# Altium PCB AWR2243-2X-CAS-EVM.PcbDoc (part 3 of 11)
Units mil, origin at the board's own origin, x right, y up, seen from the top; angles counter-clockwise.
Board outline 5118.11 x 3937.01 mil, 8 copper layers (Layer 1 - Top Layer, Layer 2 - GND, Layer 3 - Signal (Sensitive), Layer 4 - GND / Signal, Layer 5 - Signal, Layer 6 - PWR / Signal, Layer 7 - GND, Layer 8 - Bottom Layer), stack 54.8 mil thick; 629 components, 407 nets, 2243 pads, 3950 vias.
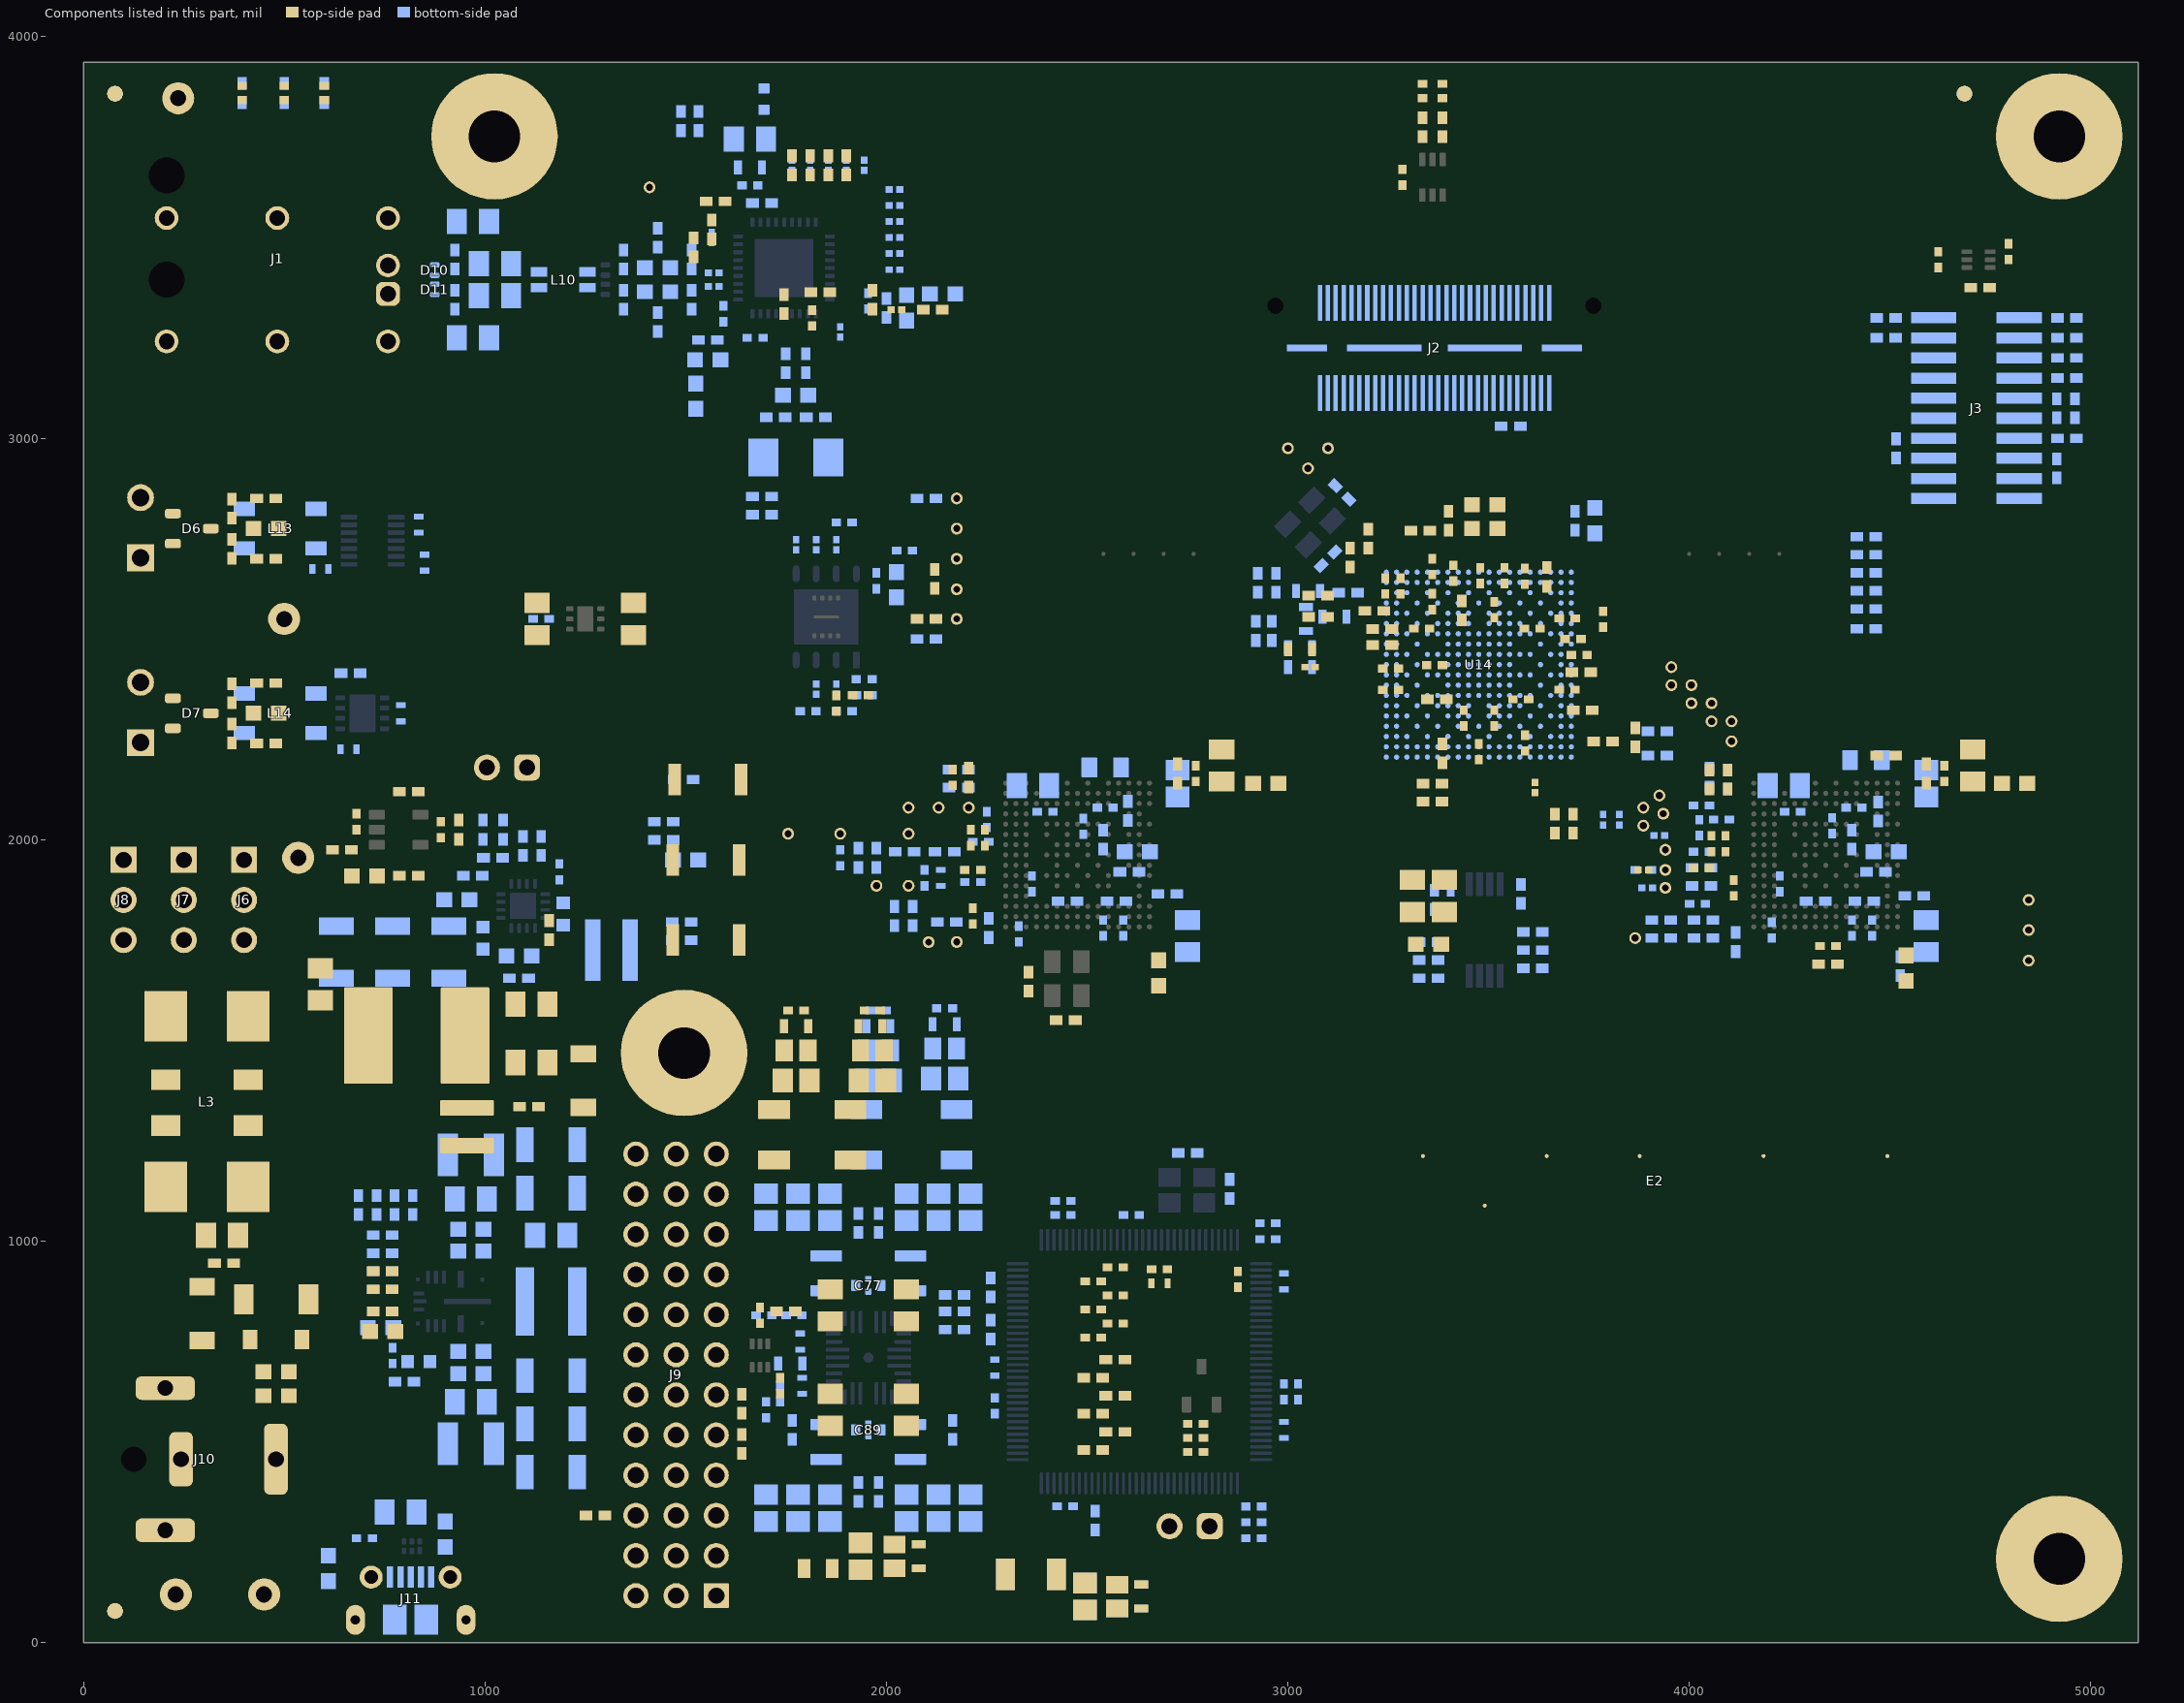
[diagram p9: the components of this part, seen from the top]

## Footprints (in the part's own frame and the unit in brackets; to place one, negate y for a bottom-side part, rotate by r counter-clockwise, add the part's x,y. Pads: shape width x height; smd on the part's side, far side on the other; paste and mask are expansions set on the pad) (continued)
Samtec_FTR-110-51-x-D-06 [mm] "Header, 1.27mm, 10x2, SMT"
  rect 2.87x0.711 smd: 1(-2.705,5.715) 2(2.705,5.715) 3(-2.705,4.445) 4(2.705,4.445) 5(-2.705,3.175) 6(2.705,3.175) 7(-2.705,1.905) 8(2.705,1.905) 9(-2.705,0.635) 10(2.705,0.635) 11(-2.705,-0.635) 12(2.705,-0.635) 13(-2.705,-1.905) 14(2.705,-1.905) 15(-2.705,-3.175) 16(2.705,-3.175) 17(-2.705,-4.445) 18(2.705,-4.445) 19(-2.705,-5.715) 20(2.705,-5.715)
  silkscreen extent -2.49,-6.35 2.49,6.7, body extent -3.76,-6.35 3.76,6.35, height 8.64
Samtec_QSH-030-01-X-D-A [mm] "Receptacle, 0.5 mm, 30x2, TH"
  rect 2.27x0.279 smd: 1(-2.865,7.25) 2(2.865,7.25) 3(-2.865,6.75) 4(2.865,6.75) 5(-2.865,6.25) 6(2.865,6.25) 7(-2.865,5.75) 8(2.865,5.75) 9(-2.865,5.25) 10(2.865,5.25) 11(-2.865,4.75) 12(2.865,4.75) 13(-2.865,4.25) 14(2.865,4.25) 15(-2.865,3.75) 16(2.865,3.75) 17(-2.865,3.25) 18(2.865,3.25) 19(-2.865,2.75) 20(2.865,2.75) 21(-2.865,2.25) 22(2.865,2.25) 23(-2.865,1.75) 24(2.865,1.75) 25(-2.865,1.25) 26(2.865,1.25) 27(-2.865,0.75) 28(2.865,0.75) 29(-2.865,0.25) 30(2.865,0.25) 31(-2.865,-0.25) 32(2.865,-0.25) 33(-2.865,-0.75) 34(2.865,-0.75) 35(-2.865,-1.25) 36(2.865,-1.25) 37(-2.865,-1.75) 38(2.865,-1.75) 39(-2.865,-2.25) 40(2.865,-2.25) 41(-2.865,-2.75) 42(2.865,-2.75) 43(-2.865,-3.25) 44(2.865,-3.25) 45(-2.865,-3.75) 46(2.865,-3.75) 47(-2.865,-4.25) 48(2.865,-4.25) 49(-2.865,-4.75) 50(2.865,-4.75) 51(-2.865,-5.25) 52(2.865,-5.25) 53(-2.865,-5.75) 54(2.865,-5.75) 55(-2.865,-6.25) 56(2.865,-6.25) 57(-2.865,-6.75) 58(2.865,-6.75) 59(-2.865,-7.25) 60(2.865,-7.25)
  round 0 hole 1.02 unplated: MH1(2.67,10.065) MH2(2.67,-10.065)
  rect 0.43x2.54 smd: MP1(0,8.065) MP4(0,-8.065)
  rect 0.43x4.7 smd: MP2(0,3.175) MP3(0,-3.175)
  silkscreen extent -3.9,-10.66 3.62,10.66, body extent -3.75,-10.64 3.75,10.67, height 3.25
SMAF [mm] "SMD, 2-Leads, Body 3.8x2.5mm"
  rect 1.24x1.89 smd: 1(-2.04,0) 2(2.04,0)
  silkscreen extent -3.4,-1.3 2.8,1.3, body extent -2.35,-1.25 2.35,1.25, height 1
SML-P1_GREEN [mm] "ROHM"
  rect 0.5x0.6 smd: 1(-0.45,0) 2(0.45,0)
  silkscreen extent -0.95,-0.3 -0.95,0.3, body extent -0.53,-0.33 0.53,0.33, height 0.25
SOD-123 [mm] "On Semi recommended land pattern"
  rect 0.915x1.22 smd: 1(-1.637,0) 2(1.637,0)
  silkscreen extent -2.74,-1.17 2.03,1.17, body extent -1.93,-0.9 1.93,0.9, height 1.35
SOT-23 [mm] "SOT23, 3-Leads, Body 2.9x1.3mm, Pitch 0.95mm, Lead Span 2.5mm, IPC Medium Density"
  rrect50% 1x0.6 smd: 1(-1.2,0.95) 2(-1.2,-0.95) 3(1.2,0)
  silkscreen extent -1.63,-1.5 0.7,1.5, body extent -1.16,-1.45 1.21,1.45, height 1
SW_SKRKAEE010 [mm] "Alps recommended land pattern"
  rect 0.8x2 smd: 1(-2.1,0) 2(2.1,0)
  silkscreen extent -1.9,-1.44 1.92,1.44, body extent -2.4,-1.45 2.4,1.45, height 1.96
TDK_ACM1211 [mm] "SMT, 4-Leads, Body 12x11mm"
  rect 2.7x3.2 smd: 1(-2.6,5.4) 2(2.6,5.4) 3(2.6,-5.4) 4(-2.6,-5.4)
  silkscreen extent -5.65,-6.15 5.65,6.15, body extent -5.65,-6.15 5.65,6.15, height 6
TDK_ACT1210 [mm] "SMD, 4-Leads, Body 3.9x2.5mm"
  rect 1.05x0.6 smd: 1(-1.525,0.5) 2(-1.525,-0.5) 3(1.525,-0.5) 4(1.525,0.5)
  silkscreen extent -1.8,-1.35 1.7,1.6, body extent -1.95,-1.35 1.95,1.35, height 2.5
TE_9-2304372-9 [mm] "Header(shrouded), 6 Power, 2 Signal, R/A, TH"
  rrect50% 1.5x1.5 hole 1: 1(-0.9,14)
  round 1.5 hole 1: 2(0.9,14) S1(-3.9,14) S2(-3.9,7) S3(-3.9,0) S4(3.9,14) S5(3.9,7) S6(3.9,0)
  round 2 hole 2.25 unplated: ALIGN1(0,0) ALIGN2(6.6,0)
  silkscreen extent -7.45,-5.15 10.3,15.95, body extent -7.45,-5.15 10.3,15.95, height 13.51
TI_Stacked_Overlay_Small [mil]
  silkscreen extent -418,-98 418,98
TP_H045P075 [mm] "TP_H0.45P0.75"
  round 0.75 hole 0.45: 1(0,0)
TSW-102-07-G-S [mm] "Samtec 100mil, 1x2, 230 mil above insulator"
  rrect50% 1.65x1.65 hole 1.016: 1(-1.27,0)
  round 1.65 hole 1.016: 2(1.27,0)
  silkscreen extent -3.17,-1.27 2.54,1.27, body extent -2.54,-1.27 2.54,1.27, height 8.38
TSW-103-07-X-S [mm] "Samtec Header, 100mil, 1x3"
  rect 1.65x1.65 hole 1.016: 1(-2.54,0)
  round 1.65 hole 1.016: 2(0,0) 3(2.54,0)
  silkscreen extent -4.57,-1.52 4.06,1.52, body extent -3.81,-1.27 3.81,1.27, height 8.38
"TX Antenna" [mm] "TX 80 Ghz Antenna"
  round 0.25 smd: "D1 - TX1"(7.976,-0.25) "D1 - TX2"(4.058,-3.385) "D1 - TX3"(0.139,-0.25) "D2 - TX1"(29.527,-0.25) "D2 - TX2"(21.691,-0.25) "D2 - TX3"(13.854,-0.25)
  Layer 1 - Top Layer region: 3.679,-3.743 3.919,-3.743 3.919,-3.135 4.196,-3.135 4.196,-4.535 4.108,-4.535 4.108,-5.735 4.307,-5.735 4.307,-6.835 4.108,-6.835 4.108,-8.035 4.507,-8.035 4.507,-9.12 4.108,-9.12 4.108,-10.32 4.657,-10.32 4.657,-11.39 4.108,-11.39 4.108,-12.59 4.808,-12.59 4.808,-13.65 4.108,-13.65 4.108,-14.85 4.808,-14.85 4.808,-15.91 4.108,-15.91 4.108,-17.11 4.657,-17.11 4.657,-18.18 4.108,-18.18 4.108,-19.38 4.507,-19.38 4.507,-20.465 4.108,-20.465 4.108,-21.665 4.307,-21.665 4.307,-22.765 3.808,-22.765 3.808,-21.665 4.008,-21.665 4.008,-20.465 3.608,-20.465 3.608,-19.38 4.008,-19.38 4.008,-18.18 3.458,-18.18 3.458,-17.11 4.008,-17.11 4.008,-15.91 3.307,-15.91 3.307,-14.85 4.008,-14.85 4.008,-13.65 3.307,-13.65 3.307,-12.59 4.008,-12.59 4.008,-11.39 3.458,-11.39 3.458,-10.32 4.008,-10.32 4.008,-9.12 3.608,-9.12 3.608,-8.035 4.008,-8.035 4.008,-6.835 3.808,-6.835 3.808,-5.735 4.008,-5.735 4.008,-4.535 3.919,-4.535 3.919,-4.02 3.679,-4.02
  Layer 1 - Top Layer region: 29.149,-0.608 29.389,-0.608 29.389,0 29.666,0 29.666,-1.4 29.577,-1.4 29.577,-2.6 29.777,-2.6 29.777,-3.7 29.577,-3.7 29.577,-4.9 29.977,-4.9 29.977,-5.985 29.577,-5.985 29.577,-7.185 30.127,-7.185 30.127,-8.255 29.577,-8.255 29.577,-9.455 30.278,-9.455 30.278,-10.515 29.577,-10.515 29.577,-11.715 30.278,-11.715 30.278,-12.775 29.577,-12.775 29.577,-13.975 30.127,-13.975 30.127,-15.045 29.577,-15.045 29.577,-16.245 29.977,-16.245 29.977,-17.33 29.577,-17.33 29.577,-18.53 29.777,-18.53 29.777,-19.63 29.278,-19.63 29.278,-18.53 29.478,-18.53 29.478,-17.33 29.078,-17.33 29.078,-16.245 29.478,-16.245 29.478,-15.045 28.928,-15.045 28.928,-13.975 29.478,-13.975 29.478,-12.775 28.777,-12.775 28.777,-11.715 29.478,-11.715 29.478,-10.515 28.777,-10.515 28.777,-9.455 29.478,-9.455 29.478,-8.255 28.928,-8.255 28.928,-7.185 29.478,-7.185 29.478,-5.985 29.078,-5.985 29.078,-4.9 29.478,-4.9 29.478,-3.7 29.278,-3.7 29.278,-2.6 29.478,-2.6 29.478,-1.4 29.389,-1.4 29.389,-0.885 29.149,-0.885
  Layer 1 - Top Layer region: 21.312,-0.608 21.552,-0.608 21.552,0 21.829,0 21.829,-1.4 21.741,-1.4 21.741,-2.6 21.94,-2.6 21.94,-3.7 21.741,-3.7 21.741,-4.9 22.14,-4.9 22.14,-5.985 21.741,-5.985 21.741,-7.185 22.29,-7.185 22.29,-8.255 21.741,-8.255 21.741,-9.455 22.441,-9.455 22.441,-10.515 21.741,-10.515 21.741,-11.715 22.441,-11.715 22.441,-12.775 21.741,-12.775 21.741,-13.975 22.29,-13.975 22.29,-15.045 21.741,-15.045 21.741,-16.245 22.14,-16.245 22.14,-17.33 21.741,-17.33 21.741,-18.53 21.94,-18.53 21.94,-19.63 21.441,-19.63 21.441,-18.53 21.641,-18.53 21.641,-17.33 21.241,-17.33 21.241,-16.245 21.641,-16.245 21.641,-15.045 21.091,-15.045 21.091,-13.975 21.641,-13.975 21.641,-12.775 20.94,-12.775 20.94,-11.715 21.641,-11.715 21.641,-10.515 20.94,-10.515 20.94,-9.455 21.641,-9.455 21.641,-8.255 21.091,-8.255 21.091,-7.185 21.641,-7.185 21.641,-5.985 21.241,-5.985 21.241,-4.9 21.641,-4.9 21.641,-3.7 21.441,-3.7 21.441,-2.6 21.641,-2.6 21.641,-1.4 21.552,-1.4 21.552,-0.885 21.312,-0.885
  Layer 1 - Top Layer region: 13.475,-0.608 13.715,-0.608 13.715,0 13.992,0 13.992,-1.4 13.904,-1.4 13.904,-2.6 14.103,-2.6 14.103,-3.7 13.904,-3.7 13.904,-4.9 14.303,-4.9 14.303,-5.985 13.904,-5.985 13.904,-7.185 14.453,-7.185 14.453,-8.255 13.904,-8.255 13.904,-9.455 14.604,-9.455 14.604,-10.515 13.904,-10.515 13.904,-11.715 14.604,-11.715 14.604,-12.775 13.904,-12.775 13.904,-13.975 14.453,-13.975 14.453,-15.045 13.904,-15.045 13.904,-16.245 14.303,-16.245 14.303,-17.33 13.904,-17.33 13.904,-18.53 14.103,-18.53 14.103,-19.63 13.604,-19.63 13.604,-18.53 13.804,-18.53 13.804,-17.33 13.404,-17.33 13.404,-16.245 13.804,-16.245 13.804,-15.045 13.254,-15.045 13.254,-13.975 13.804,-13.975 13.804,-12.775 13.103,-12.775 13.103,-11.715 13.804,-11.715 13.804,-10.515 13.103,-10.515 13.103,-9.455 13.804,-9.455 13.804,-8.255 13.254,-8.255 13.254,-7.185 13.804,-7.185 13.804,-5.985 13.404,-5.985 13.404,-4.9 13.804,-4.9 13.804,-3.7 13.604,-3.7 13.604,-2.6 13.804,-2.6 13.804,-1.4 13.715,-1.4 13.715,-0.885 13.475,-0.885
  Layer 1 - Top Layer region: 7.597,-0.608 7.837,-0.608 7.837,0 8.114,0 8.114,-1.4 8.026,-1.4 8.026,-2.6 8.226,-2.6 8.226,-3.7 8.026,-3.7 8.026,-4.9 8.426,-4.9 8.426,-5.985 8.026,-5.985 8.026,-7.185 8.575,-7.185 8.575,-8.255 8.026,-8.255 8.026,-9.455 8.726,-9.455 8.726,-10.515 8.026,-10.515 8.026,-11.715 8.726,-11.715 8.726,-12.775 8.026,-12.775 8.026,-13.975 8.575,-13.975 8.575,-15.045 8.026,-15.045 8.026,-16.245 8.426,-16.245 8.426,-17.33 8.026,-17.33 8.026,-18.53 8.226,-18.53 8.226,-19.63 7.726,-19.63 7.726,-18.53 7.926,-18.53 7.926,-17.33 7.526,-17.33 7.526,-16.245 7.926,-16.245 7.926,-15.045 7.376,-15.045 7.376,-13.975 7.926,-13.975 7.926,-12.775 7.225,-12.775 7.225,-11.715 7.926,-11.715 7.926,-10.515 7.225,-10.515 7.225,-9.455 7.926,-9.455 7.926,-8.255 7.376,-8.255 7.376,-7.185 7.926,-7.185 7.926,-5.985 7.526,-5.985 7.526,-4.9 7.926,-4.9 7.926,-3.7 7.726,-3.7 7.726,-2.6 7.926,-2.6 7.926,-1.4 7.837,-1.4 7.837,-0.885 7.597,-0.885
  Layer 1 - Top Layer region: -0.24,-0.608 0,-0.608 0,0 0.277,0 0.277,-1.4 0.189,-1.4 0.189,-2.6 0.389,-2.6 0.389,-3.7 0.189,-3.7 0.189,-4.9 0.589,-4.9 0.589,-5.985 0.189,-5.985 0.189,-7.185 0.738,-7.185 0.738,-8.255 0.189,-8.255 0.189,-9.455 0.889,-9.455 0.889,-10.515 0.189,-10.515 0.189,-11.715 0.889,-11.715 0.889,-12.775 0.189,-12.775 0.189,-13.975 0.738,-13.975 0.738,-15.045 0.189,-15.045 0.189,-16.245 0.589,-16.245 0.589,-17.33 0.189,-17.33 0.189,-18.53 0.389,-18.53 0.389,-19.63 -0.111,-19.63 -0.111,-18.53 0.089,-18.53 0.089,-17.33 -0.311,-17.33 -0.311,-16.245 0.089,-16.245 0.089,-15.045 -0.461,-15.045 -0.461,-13.975 0.089,-13.975 0.089,-12.775 -0.611,-12.775 -0.611,-11.715 0.089,-11.715 0.089,-10.515 -0.611,-10.515 -0.611,-9.455 0.089,-9.455 0.089,-8.255 -0.461,-8.255 -0.461,-7.185 0.089,-7.185 0.089,-5.985 -0.311,-5.985 -0.311,-4.9 0.089,-4.9 0.089,-3.7 -0.111,-3.7 -0.111,-2.6 0.089,-2.6 0.089,-1.4 0,-1.4 0,-0.885 -0.24,-0.885
WEEE_Minimum [mil] "WEEElie bin"
  silkscreen extent -95,-172 99,104
XAL5020 [mm] "Coilcraft XAL5020"
  rect 1.18x4.34 smd: 1(-1.655,0) 2(1.655,0)
  silkscreen extent -2.8,-2.9 2.8,2.9, body extent -2.74,-2.84 2.74,2.84, height 3.1
XEL4030_310 [mm] "SMD, 2-Leads, Body 4x4mm, Pitch 2.37mm"
  rect 0.98x3.9 smd: 1(-1.185,0) 2(1.185,0)
  silkscreen extent -2.3,-2.3 2.3,2.3, body extent -2.15,-2.15 2.15,2.15, height 3.1
XTAL_ABM3 [mm] "Abracon recommended land pattern 12.28.10"
  rect 1.9x2.4 smd: 1(-2.05,0) 2(2.05,0)
  silkscreen extent -2.67,-1.78 2.67,1.78, body extent -2.6,-1.7 2.6,1.7, height 1.3
ZCE0285A-MFG [mil]
  round 13 smd paste+0 mask+2: A1(-230.32,230.32) A2(-204.72,230.32) A3(-179.13,230.32) A4(-153.54,230.32) A5(-127.95,230.32) A6(-102.36,230.32) A7(-76.77,230.32) A8(-51.18,230.32) A9(-25.59,230.32) A10(0,230.32) A11(25.59,230.32) A12(51.18,230.32) A13(76.77,230.32) A14(102.36,230.32) A15(127.95,230.32) A16(153.54,230.32) A17(179.13,230.32) A18(204.72,230.32) A19(230.31,230.32) B1(-230.32,204.72) B2(-204.72,204.72) B3(-179.13,204.72) B4(-153.54,204.72) B5(-127.95,204.72) B6(-102.36,204.72) B7(-76.77,204.72) B8(-51.18,204.72) B9(-25.59,204.72) B10(0,204.72) B11(25.59,204.72) B12(51.18,204.72) B13(76.77,204.72) B14(102.36,204.72) B15(127.95,204.72) B16(153.54,204.72) B17(179.13,204.72) B18(204.72,204.72) B19(230.31,204.72) C1(-230.32,179.13) C2(-204.72,179.13) C3(-179.13,179.13) C5(-127.95,179.13) C7(-76.77,179.13) C9(-25.59,179.13) C11(25.59,179.13) C13(76.77,179.13) C15(127.95,179.13) C17(179.13,179.13) C18(204.72,179.13) C19(230.31,179.13) D1(-230.32,153.54) D2(-204.72,153.54) D4(-153.54,153.54) D6(-102.36,153.54) D8(-51.18,153.54) D10(0,153.54) D12(51.18,153.54) D14(102.36,153.54) D16(153.54,153.54) D18(204.72,153.54) D19(230.31,153.54) E1(-230.32,127.95) E2(-204.72,127.95) E3(-179.13,127.95) E5(-127.95,127.95) E7(-76.77,127.95) E8(-51.18,127.95) E9(-25.59,127.95) E11(25.59,127.95) E12(51.18,127.95) E13(76.77,127.95) E15(127.95,127.95) E17(179.13,127.95) E18(204.72,127.95) E19(230.31,127.95) F1(-230.32,102.36) F2(-204.72,102.36) F4(-153.54,102.36) F6(-102.36,102.36) F7(-76.77,102.36) F8(-51.18,102.36) F9(-25.59,102.36) F11(25.59,102.36) F12(51.18,102.36) F13(76.77,102.36) F14(102.36,102.36) F16(153.54,102.36) F18(204.72,102.36) F19(230.31,102.36) G1(-230.32,76.77) G2(-204.72,76.77) G3(-179.13,76.77) G5(-127.95,76.77) G6(-102.36,76.77) G7(-76.77,76.77) G8(-51.18,76.77) G9(-25.59,76.77) G10(0,76.77) G11(25.59,76.77) G12(51.18,76.77) G13(76.77,76.77) G14(102.36,76.77) G15(127.95,76.77) G17(179.13,76.77) G18(204.72,76.77) G19(230.31,76.77) H1(-230.32,51.18) H2(-204.72,51.18) H4(-153.54,51.18) H7(-76.77,51.18) H8(-51.18,51.18) H9(-25.59,51.18) H10(0,51.18) H11(25.59,51.18) H12(51.18,51.18) H13(76.77,51.18) H16(153.54,51.18) H18(204.72,51.18) H19(230.31,51.18) J1(-230.32,25.59) J2(-204.72,25.59) J3(-179.13,25.59) J5(-127.95,25.59) J6(-102.36,25.59) J7(-76.77,25.59) J8(-51.18,25.59) J9(-25.59,25.59) J10(0,25.59) J11(25.59,25.59) J12(51.18,25.59) J13(76.77,25.59) J14(102.36,25.59) J15(127.95,25.59) J17(179.13,25.59) J18(204.72,25.59) J19(230.31,25.59) K1(-230.32,0) K2(-204.72,0) K4(-153.54,0) K7(-76.77,0) K8(-51.18,0) K9(-25.59,0) K10(0,0) K11(25.59,0) K12(51.18,0) K13(76.77,0) K16(153.54,0) K18(204.72,0) K19(230.31,0) L1(-230.32,-25.59) L2(-204.72,-25.59) L3(-179.13,-25.59) L5(-127.95,-25.59) L6(-102.36,-25.59) L7(-76.77,-25.59) L8(-51.18,-25.59) L9(-25.59,-25.59) L10(0,-25.59) L11(25.59,-25.59) L12(51.18,-25.59) L13(76.77,-25.59) L14(102.36,-25.59) L15(127.95,-25.59) L17(179.13,-25.59) L18(204.72,-25.59) L19(230.31,-25.59) M1(-230.32,-51.18) M2(-204.72,-51.18) M4(-153.54,-51.18) M7(-76.77,-51.18) M8(-51.18,-51.18) M9(-25.59,-51.18) M10(0,-51.18) M11(25.59,-51.18) M12(51.18,-51.18) M13(76.77,-51.18) M16(153.54,-51.18) M18(204.72,-51.18) M19(230.31,-51.18) N1(-230.32,-76.77) N2(-204.72,-76.77) N3(-179.13,-76.77) N5(-127.95,-76.77) N6(-102.36,-76.77) N7(-76.77,-76.77) N8(-51.18,-76.77) N9(-25.59,-76.77) N10(0,-76.77) N11(25.59,-76.77) N12(51.18,-76.77) N13(76.77,-76.77) N14(102.36,-76.77) N15(127.95,-76.77) N17(179.13,-76.77) N18(204.72,-76.77) N19(230.31,-76.77) P1(-230.32,-102.36) P2(-204.72,-102.36) P4(-153.54,-102.36) P6(-102.36,-102.36) P7(-76.77,-102.36) P8(-51.18,-102.36) P9(-25.59,-102.36) P11(25.59,-102.36) P12(51.18,-102.36) P13(76.77,-102.36) P14(102.36,-102.36) P16(153.54,-102.36) P18(204.72,-102.36) P19(230.31,-102.36) R1(-230.32,-127.95) R2(-204.72,-127.95) R3(-179.13,-127.95) R5(-127.95,-127.95) R7(-76.77,-127.95) R8(-51.18,-127.95) R9(-25.59,-127.95) R11(25.59,-127.95) R12(51.18,-127.95) R13(76.77,-127.95) R15(127.95,-127.95) R17(179.13,-127.95) R18(204.72,-127.95) R19(230.31,-127.95) T1(-230.32,-153.54) T2(-204.72,-153.54) T4(-153.54,-153.54) T6(-102.36,-153.54) T8(-51.18,-153.54) T10(0,-153.54) T12(51.18,-153.54) T14(102.36,-153.54) T16(153.54,-153.54) T18(204.72,-153.54) T19(230.31,-153.54) U1(-230.32,-179.13) U2(-204.72,-179.13) U3(-179.13,-179.13) U5(-127.95,-179.13) U7(-76.77,-179.13) U9(-25.59,-179.13) U11(25.59,-179.13) U13(76.77,-179.13) U15(127.95,-179.13) U17(179.13,-179.13) U18(204.72,-179.13) U19(230.31,-179.13) V1(-230.32,-204.72) V2(-204.72,-204.72) V3(-179.13,-204.72) V4(-153.54,-204.72) V5(-127.95,-204.72) V6(-102.36,-204.72) V7(-76.77,-204.72) V8(-51.18,-204.72) V9(-25.59,-204.72) V10(0,-204.72) V11(25.59,-204.72) V12(51.18,-204.72) V13(76.77,-204.72) V14(102.36,-204.72) V15(127.95,-204.72) V16(153.54,-204.72) V17(179.13,-204.72) V18(204.72,-204.72) V19(230.31,-204.72) W1(-230.32,-230.31) W2(-204.72,-230.31) W3(-179.13,-230.31) W4(-153.54,-230.31) W5(-127.95,-230.31) W6(-102.36,-230.31) W7(-76.77,-230.31) W8(-51.18,-230.31) W9(-25.59,-230.31) W10(0,-230.31) W11(25.59,-230.31) W12(51.18,-230.31) W13(76.77,-230.31) W14(102.36,-230.31) W15(127.95,-230.31) W16(153.54,-230.31) W17(179.13,-230.31) W18(204.72,-230.31) W19(230.31,-230.31)
  silkscreen extent -295,-258 258,258, body extent -256,-256 256,256, height 51

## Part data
C1 C9 C10 C20 C24 C99 C106 C107 C111 C153 C170 C175 C180 C181 C211 C215 C223: library part CMP-0006351-2, "CAP, CERM, 0.1 uF, 16 V, +/- 10%, X7R, 0402", Cap_Case=0402, Manufacturer=MuRata, Supplier Part Number 1=490-4759-2-ND, TempCo=X7R, Tolerance_%=10%, Value1=Unknown, Value2=16V, ValueDisplayed=0.1uF
C2: library part CMP-0078241-1, "CAP, CERM, 0.1 µF, 10 V,+/- 10%, X7R, 0402", Cap_Case=0402, Manufacturer=Kemet, PartNumber=C0402C104K8RACTU, Supplier Part Number 1=399-3520-1-ND, TempCo=X7R, Tolerance_%=10%, Value2=10V, ValueDisplayed=0.1µF
C3 C7 C30 C38 C101 C105: library part CMP-0006438-2, "CAP, CERM, 22 pF, 50 V, +/- 1%, C0G/NP0, 0402", Cap_Case=0402, Manufacturer=MuRata, Supplier Part Number 1=490-8589-1-ND, TempCo=C0G/NP0, Tolerance_%=1%, Value1=Unknown, Value2=50V, ValueDisplayed=22pF
C4 C6 C84 C116: library part CMP-0007134-5, "CAP, CERM, 2.2 uF, 6.3 V, +/- 10%, X7R, AEC-Q200 Grade 1, 0603", Cap_Case=0603, Manufacturer=MuRata, Supplier Part Number 1=490-5316-1-ND, TempCo=X7R, Tolerance_%=10%, Value1=Unknown, Value2=6.3V, ValueDisplayed=2.2uF
C5 C35: library part CMP-0007146-2, "CAP, CERM, 4700 pF, 50 V, +/- 10%, X7R, AEC-Q200 Grade 1, 0603", Cap_Case=0603, Manufacturer=MuRata, Supplier Part Number 1=490-4932-1-ND, TempCo=X7R, Tolerance_%=10%, Value1=Unknown, Value2=50V, ValueDisplayed=4700pF
C8 C11 C12 C13 C14 C15 C19 C21 C22 C23 C26 C27 C28 C31 C32 C34 C36 C37 C39 C42 C43 C44 C45 C46 C50 C51 C52 C53 C56 C57 C64 C65 C138 C139 C140 C141 C142 C143 C146 C147 C148 C149 C156 C157 C160 C161 C163 C164 C165 C166 C171 C172 C173 C174 C184 C185: library part CMP-0078265-1, "CAP, CERM, 0.22 µF, 16 V,+/- 10%, X7R, AEC-Q200 Grade 1, 0402", Cap_Case=0402, Manufacturer=MuRata, Supplier Part Number 1=490-10671-1-ND, TempCo=X7R, Tolerance_%=10%, Value2=16V, ValueDisplayed=0.22µF
C16 C17 C40 C41 C54 C69 C70 C78 C79 C86 C87 C93 C96 C98 C131 C132 C133 C134 C135 C136 C168 C169 C188 C189 C240: library part CMP-0008017-2, "CAP, CERM, 10 uF, 10 V, +/- 10%, X7R, 0805", Cap_Case=0805, Manufacturer=MuRata, Supplier Part Number 1=490-10674-1-ND, TempCo=X7R, Tolerance_%=10%, Value1=Unknown, Value2=10V, ValueDisplayed=10uF
C18 C29 C33 C112 C242 C244: library part CMP-0006324-2, "CAP, CERM, 0.01 uF, 50 V, +/- 10%, X7R, AEC-Q200 Grade 1, 0402", Cap_Case=0402, Manufacturer=TDK, Supplier Part Number 1=445-6893-1-ND, TempCo=X7R, Tolerance_%=10%, Value1="0.333065 ohm", Value2=50V, ValueDisplayed=0.01uF
C25 C67 C68 C94 C97 C123 C125 C126 C127 C128 C186 C187 C241 C243: library part CMP-0079154-1, "CAP, CERM, 1 µF, 16 V,+/- 10%, X7R, AEC-Q200 Grade 1, 0603", Cap_Case=0603, Manufacturer=MuRata, Supplier Part Number 1=490-12657-1-ND, TempCo=X7R, Tolerance_%=10%, Value2=16V, ValueDisplayed=1µF
C47: library part CMP-0006624-2, "CAP, CERM, 1 uF, 6.3 V, +/- 20%, X7R, 0402", Cap_Case=0402, Manufacturer=MuRata, Supplier Part Number 1=490-9665-1-ND, TempCo=X7R, Tolerance_%=20%, Value1=Unknown, Value2=6.3V, ValueDisplayed=1uF
C48 C221: library part CMP-0006302-2, "CAP, CERM, 2.2 uF, 10 V, +/- 10%, X7S, 0402", Cap_Case=0402_065, Manufacturer=TDK, Supplier Part Number 1=445-9097-1-ND, TempCo=X7S, Tolerance_%=10%, Value1="0.005925 ohm", Value2=10V, ValueDisplayed=2.2uF
C49: library part CMP-0006242-2, "CAP, CERM, 33 pF, 50 V, +/- 5%, C0G/NP0, 0402", Cap_Case=0402, Manufacturer=Kemet, Supplier Part Number 1=399-1017-1-ND, TempCo=C0G/NP0, Tolerance_%=5%, Value1=Unknown, Value2=50V, ValueDisplayed=33pF
C55: library part CMP-0008017-2, "CAP, CERM, 10 uF, 10 V, +/- 10%, X7R, 0805", Cap_Case=0805, Manufacturer=MuRata, PartNumber=GCM21BR71A106KE22L, Supplier Part Number 1=490-10674-1-ND, TempCo=X7R, Tolerance_%=10%, Value1=Unknown, Value2=10V, ValueDisplayed=10uF
C58 C59 C120 C150 C151: library part CMP-0007136-5, "CAP, CERM, 1 uF, 16 V, +/- 10%, X7R, AEC-Q200 Grade 1, 0603", Cap_Case=0603, Manufacturer=MuRata, Supplier Part Number 1=490-5241-6-ND, TempCo=X7R, Tolerance_%=10%, Value1=Unknown, Value2=16V, ValueDisplayed=1uF
C60 C63 C71 C75 C203 C224: library part CMP-0007977-2, "CAP, CERM, 2.2 uF, 50 V, +/- 10%, X7R, AEC-Q200 Grade 1, 0805", Cap_Case=0805, Manufacturer=TDK, Supplier Part Number 1=445-174216-1-ND, TempCo=X7R, Tolerance_%=10%, Value1="0.003288 ohm", Value2=50V, ValueDisplayed=2.2uF
C61: library part CMP-0006200-2, "CAP, CERM, 100 pF, 16 V, +/- 10%, X7R, 0402", Cap_Case=0402, Manufacturer=AVX, Supplier Part Number 1=478-7887-1-ND, TempCo=X7R, Tolerance_%=10%, Value1=Unknown, Value2=16V, ValueDisplayed=100pF
C62 C66 C115 C118: library part CMP-0006367-2, "CAP, CERM, 4.7 pF, 50 V, +/- 2%, C0G/NP0, 0402", Cap_Case=0402, Manufacturer=MuRata, Supplier Part Number 1=490-8102-1-ND, TempCo=C0G/NP0, Tolerance_%=2%, Value1=Unknown, Value2=50V, ValueDisplayed=4.7pF
C72 C81: library part CMP-0008702-2, "CAP, CERM, 4.7 uF, 50 V, +/- 10%, X7R, 1206", Cap_Case=1206_180, Manufacturer=TDK, Supplier Part Number 1=445-8032-1-ND, TempCo=X7R, Tolerance_%=10%, Value1="0.003158 ohm", Value2=50V, ValueDisplayed=4.7uF
C73 C74 C92 C95 C190 C191 C197 C198 C199 C200 C201 C202 C230 C231 C232 C233 C234 C235 C239: library part CMP-0008015-1, "CAP, CERM, 22 uF, 6.3 V, +/- 20%, X7T, AEC-Q200 Grade 1, 0805", Cap_Case=0805, Manufacturer=MuRata, TempCo=X7T, Tolerance_%=20%, Value1=Unknown, Value2=6.3V, ValueDisplayed=22uF
C76 C82 C90 C159 C204 C205 C208 C222 C225 C237: library part CMP-0078241-1, "CAP, CERM, 0.1 µF, 10 V,+/- 10%, X7R, 0402", Cap_Case=0402, Manufacturer=Kemet, Supplier Part Number 1=399-3520-1-ND, TempCo=X7R, Tolerance_%=10%, Value2=10V, ValueDisplayed=0.1µF
C77 C89: library part CMP-0088247-2, "3 Terminals Low ESL Chip Multilayer Ceramic Capacitors for Automotive", Manufacturer=Murata, Tolerance_%=20%, ValueDisplayed=1uF
C80 C218 C228: library part CMP-0006349-2, "CAP, CERM, 1 uF, 10 V, +/- 10%, X7S, AEC-Q200 Grade 1, 0402", Cap_Case=0402, Manufacturer=MuRata, Supplier Part Number 1=81-GCM155C71A105KE8D, TempCo=X7S, Tolerance_%=10%, Value1=Unknown, Value2=10V, ValueDisplayed=1uF
C83: library part CMP-0007069-4, "CAP, CERM, 10 pF, 50 V, +/- 5%, C0G/NP0, AEC-Q200 Grade 1, 0603", Cap_Case=0603, Manufacturer=TDK, Supplier Part Number 1=445-5628-1-ND, TempCo=C0G/NP0, Tolerance_%=5%, Value1=Unknown, Value2=50V, ValueDisplayed=10pF
C85 C88: library part CMP-0007104-4, "CAP, CERM, 0.1 uF, 50 V, +/- 10%, X8R, AEC-Q200 Grade 0, 0603", Cap_Case=0603, Manufacturer=TDK, Supplier Part Number 1=445-12606-1-ND, TempCo=X8R, Tolerance_%=10%, Value1=Unknown, Value2=50V, ValueDisplayed=0.1uF
C91 C210 C238: library part CMP-0078218-1, "CAP, CERM, 0.01 µF, 16 V,+/- 10%, X7R, 0402", Cap_Case=0402, Manufacturer=Kemet, Supplier Part Number 1=399-1038-1-ND, TempCo=X7R, Tolerance_%=10%, Value2=16V, ValueDisplayed=0.01µF
C100 C108: library part CMP-0006467-2, "CAP, CERM, 47 pF, 50 V, +/- 1%, C0G/NP0, 0402", Cap_Case=0402, Manufacturer=MuRata, Supplier Part Number 1=490-6241-1-ND, TempCo=C0G/NP0, Tolerance_%=1%, Value1=Unknown, Value2=50V, ValueDisplayed=47pF
C102 C103: library part CMP-0007969-2, "CAP, CERM, 0.1 uF, 100 V, +/- 10%, X7R, AEC-Q200 Grade 1, 0805", Cap_Case=0805, Manufacturer=TDK, Supplier Part Number 1=445-5827-1-ND, TempCo=X7R, Tolerance_%=10%, Value1="0.020726 ohm", Value2=100V, ValueDisplayed=0.1uF
C104 C110 C206 C220: library part CMP-0007097-4, "CAP, CERM, 0.47 uF, 50 V, +/- 10%, X7R, AEC-Q200 Grade 1, 0603", Cap_Case=0603, Manufacturer=TDK, Supplier Part Number 1=445-172475-1-ND, TempCo=X7R, Tolerance_%=10%, Value1=Unknown, Value2=50V, ValueDisplayed=0.47uF
C109: library part CMP-0079078-1, "CAP, CERM, 4700 pF, 50 V,+/- 10%, X7R, AEC-Q200 Grade 1, 0805", Cap_Case=0805, Manufacturer=MuRata, Supplier Part Number 1=490-6059-1-ND, TempCo=X7R, Tolerance_%=10%, Value2=50V, ValueDisplayed=4700pF
C113 C114: library part CMP-0860920-1, "CAP, CERM, 27 pF, 50 V,+/- 5%, C0G/NP0, AEC-Q200 Grade 1, 0402", Cap_Case=0402, Manufacturer=MuRata, TempCo=C0G/NP0, Tolerance_%=5%, Value2=50V, ValueDisplayed=27pF
C117 C119 C121 C129 C130: "CAP, CERM, 0.1 µF, 16 V, +/- 10%, X7R, 0402", Cap_Case=0402, Manufacturer=AVX, Supplier Part Number 1=478-7888-1-ND, TempCo=X7R, Tolerance_%=10, Value1=Unknown, Value2=16V, ValueDisplayed=0.1µF
C122: library part CMP-0006325-2, "CAP, CERM, 0.1 uF, 50 V, +/- 10%, X7R, AEC-Q200 Grade 1, 0402", Cap_Case=0402, Manufacturer=TDK, Supplier Part Number 1=445-6899-1-ND, TempCo=X7R, Tolerance_%=10%, Value1="0.039064 ohm", Value2=50V, ValueDisplayed=0.1uF
C124 C154 C155: library part CMP-0006330-2, "CAP, CERM, 0.047 uF, 50 V, +/- 10%, X7R, AEC-Q200 Grade 1, 0402", Cap_Case=0402, Manufacturer=TDK, Supplier Part Number 1=445-6897-1-ND, TempCo=X7R, Tolerance_%=10%, Value1="0.06407 ohm", Value2=50V, ValueDisplayed=0.047uF
C137 C182: library part Capacitor, "Cap, Cer-X7R, 2200pF, 50V, 10%, 0402", Alternate Manufacturer=-, Manufacturer="Taiyo Yuden", Operating Temperature="-55°C ~ 125°C", PART Name=SCH_LIB\CAP_NP, Supplier Part Number 1=587-1221-1-ND, TempCo=X7R, Tolerance_%=±10%
C144: library part CMP-0006230-1, "CAP, CERM, 100 pF, 50 V, +/- 10%, X7R, 0402", Cap_Case=0402, Manufacturer="Wurth Elektronik", Supplier Part Number 1=732-7550-1-ND, TempCo=X7R, Tolerance_%=10%, Value1=Unknown, Value2=50V, ValueDisplayed=100pF
C145: library part CMP-0006691-2, "CAP, CERM, 470 pF, 50 V, +/- 10%, X7R, 0402", Cap_Case=0402, Manufacturer=MuRata, Supplier Part Number 1=490-1300-1-ND, TempCo=X7R, Tolerance_%=10%, Value1=Unknown, Value2=50V, ValueDisplayed=470pF
C152: library part CMP-0007433-4, "CAP, CERM, 0.01 uF, 50 V, +/- 10%, X7R, 0603", Cap_Case=0603, Manufacturer=MuRata, Supplier Part Number 1=490-1512-1-ND, TempCo=X7R, Tolerance_%=10%, Value1=Unknown, Value2=50V, ValueDisplayed=0.01uF
C158: library part CMP-0007134-5, "CAP, CERM, 2.2 uF, 6.3 V, +/- 10%, X7R, AEC-Q200 Grade 1, 0603", Cap_Case=0603, Manufacturer=MuRata, PartNumber=GCM188R70J225KE22D, Supplier Part Number 1=490-5316-1-ND, TempCo=X7R, Tolerance_%=10%, Value1=Unknown, Value2=6.3V, ValueDisplayed=2.2uF
C162 C183: library part CMP-0084284-1, "CAP, CERM, 2.2 µF, 10 V,+/- 10%, X7R, AEC-Q200 Grade 1, 0603", Cap_Case=0603, Manufacturer=MuRata, TempCo=X7R, Tolerance_%=10%, Value2=10V, ValueDisplayed=2.2µF
C167: library part CMP-0007144-4, "CAP, CERM, 0.1 uF, 50 V, +/- 10%, X7R, 0603", Cap_Case=0603, Manufacturer=MuRata, Supplier Part Number 1=490-4779-1-ND, TempCo=X7R, Tolerance_%=10%, Value1="0.02 ohm", Value2=50V, ValueDisplayed=0.1uF
C176 C177 C178: library part CMP-0009175-2, "CAP, CERM, 10 uF, 25 V, +/- 10%, X7R, AEC-Q200 Grade 1, 1210", Cap_Case=1210, Manufacturer=MuRata, Supplier Part Number 1=490-4798-1-ND, TempCo=X7R, Tolerance_%=10%, Value1=Unknown, Value2=25V, ValueDisplayed=10uF
C179: library part CMP-0007139-4, "CAP, CERM, 1 uF, 25 V, +/- 10%, X7R, AEC-Q200 Grade 1, 0603", Cap_Case=0603, Manufacturer=MuRata, Supplier Part Number 1=490-10673-1-ND, TempCo=X7R, Tolerance_%=10%, Value1=Unknown, Value2=25V, ValueDisplayed=1uF
C192 C196 C216 C226 C229: library part CMP-0009154-2, "CAP, CERM, 22 uF, 16 V, +/- 20%, X7R, AEC-Q200 Grade 1, 1210", Cap_Case=1210_280, Manufacturer=TDK, PartNumber=CGA6P1X7R1C226M250AC, Supplier Part Number 1=445-5723-1-ND, TempCo=X7R, Tolerance_%=20%, Value1="0.002582 ohm", Value2=16V, ValueDisplayed=22uF
C193 C227: library part CMP-0009226-3, "CAP, CERM, 10 uF, 50 V, +/- 10%, X7R, 1210", Cap_Case=1210, Manufacturer=MuRata, Supplier Part Number 1=490-6544-1-ND, TempCo=X7R, Tolerance_%=10%, Value1=Unknown, Value2=50V, ValueDisplayed=10uF
C194 C195: library part CMP-0087060-3, "Cap Ceramic 8pF 50V C0G 0.5pF SMD 0402 125C Paper T/R", Manufacturer="Murata Electronics North America", TempCo=30ppm/°C
C207: library part CMP-0007728-2, "CAP, CERM, 1 uF, 25 V, +/- 10%, X7R, 0805", Cap_Case=0805, Manufacturer=Kemet, PartNumber=C0805C105K3RACTU, Supplier Part Number 1=399-8004-1-ND, TempCo=X7R, Tolerance_%=10%, Value1=Unknown, Value2=25V, ValueDisplayed=1uF
C209 C214: library part CMP-0007046-5, "CAP, CERM, 0.15 uF, 50 V, +/- 10%, X7R, 0603", Cap_Case=0603, Manufacturer=TDK, Supplier Part Number 1=445-7406-1-ND, TempCo=X7R, Tolerance_%=10%, Value1="0.028863 ohm", Value2=50V, ValueDisplayed=0.15uF
C212: library part CMP-0007365-4, "CAP, CERM, 1 uF, 10 V, +/- 10%, X7R, 0603", Cap_Case=0603, Manufacturer=MuRata, PartNumber=GRM188R71A105KA61D, Supplier Part Number 1=490-3899-1-ND, TempCo=X7R, Tolerance_%=10%, Value1="0.011 ohm", Value2=10V, ValueDisplayed=1uF
C213 C219: library part CMP-0064967-2, "CAP, CERM, 0.47 uF, 10 V,+/- 10%, X7S, 0402", Cap_Case=0402, Manufacturer=MuRata, Supplier Part Number 1=490-14427-1-ND, TempCo=X7S, Tolerance_%=10%, Value1=Unknown, Value2=10V, ValueDisplayed=0.47uF
C217: library part CMP-0006981-4, "CAP, CERM, 0.1 uF, 10 V, +/- 10%, X7R, 0603", Cap_Case=0603, Manufacturer=Kemet, PartNumber=C0603X104K8RACTU, Supplier Part Number 1=399-5343-1-ND, TempCo=X7R, Tolerance_%=10%, Value1=Unknown, Value2=10V, ValueDisplayed=0.1uF
C236: library part CMP-0007995-2, "CAP, CERM, 10 uF, 16 V, +/- 10%, X7R, 0805", Cap_Case=0805, Manufacturer="Samsung Electro-Mechanics", TempCo=X7R, Tolerance_%=10%, Value1=Unknown, Value2=16V, ValueDisplayed=10uF
"CAUTION HOT SURFACE1": library part CMP-0074837-1, "IEC 61010-1 Hot Surface Warning"
D1 D4: library part CMP-0002839-2, "LED, Yellow, SMD", Color=yellow, Manufacturer=Rohm, Value1=W, Value2=2.1V
D2 D3: library part CMP-0002841-1, "LED, Orange, SMD", Color=orange, Manufacturer=Rohm, Supplier Part Number 1=511-1590-1-ND, Value1=W, Value2=2.1V
D5: library part CMP-0002873-2, "LED, Green, SMD", Color=green, Manufacturer=Rohm, Value1=W, Value2=2.2V
D6 D7: library part CMP-0005920-3, "Diode, TVS, Bi, 24 V, 70 Vc, AEC-Q101, SOT-23", Manufacturer="NXP Semiconductor", Value1=200W
D8: library part CMP-0028823-2, "Diode, Schottky, 30 V, 5 A, AEC-Q101, SMAF", Manufacturer="Fairchild Semiconductor", Value1=5A, Value2=0.54V
D9: library part CMP-0005735-3, "Diode, TVS, Bi, 28 V, 45.4 Vc, AEC-Q101, SOD-123", Manufacturer="Comchip Technology", Value1=200W
D10 D11: library part CMP-0073591-4, "Automotive 1-Channel Ultra-Low-Capacitance IEC ESD Protection Diode, DPY0002A (X1SON-2)", Alternate Manufacturer="Texas Instruments", Alternate PartNumber=TPD1E05U06QDPYTQ1, Operating Temperature Range="-40 to 125 C", Rating=Automotive
"ESD Susceptible1": library part CMP-0074840-1, "ESD Susceptible Symbol"
FB1: library part CMP-0089848-1, "600 Ohms @ 100MHz 1 Power Line Ferrite Bead 0603 (1608 Metric) 1.3A 150mOhm", Digikey Part Number=490-13259-1-ND, Impedance At Frequency="600Ω @ 100MHz", Manufacturer=Murata, Mouser Part Number=81-BLM18KG601SH1D, Operating Temperature Range="-55°C to +125°C", Test Frequency=100MHz, Tolerance_%=25%
FID1 FID2 FID3 FID4 FID5 FID6: library part CMP-0077181-1, "Fiducial mark.  There is nothing to buy or mount.", Manufacturer=N/A
H1 H2 H3 H4: "Machine Screw, Round, #4-40 x 1/4, Nylon, Philips panhead", DigiKeyPartNumber=H542-ND, Manufacturer="B&F Fastener Supply"
J1: library part CMP-0078655-1, "1 Port Header Assembly, TH", Color=Blue, Manufacturer="TE Connectivity"
J2: library part CMP-0075524-1, "Receptacle, 0.5 mm, 30x2, Gold, TH", Color=Black, Manufacturer=Samtec, Supplier Part Number 1=SAM8180-ND
J3: library part CMP-0075640-2, "Header, 1.27mm, 10x2, Tin, SMT", Color=Black, Current_A=3.1A, Manufacturer=Samtec, Supplier Part Number 1=SAM8792-ND
J4 J5: library part CMP-0055472-1, "Conn Term Block, 2POS, 3.81mm, TH", Manufacturer="Phoenix Contact", Supplier Part Number 1=277-1947-ND
J6 J7 J8: library part CMP-0075407-1, "Header, 100mil, 3x1, Gold, TH", Color=Black, Current_A=6.3A, Manufacturer=Samtec, Supplier Part Number 1=SAM1029-03-ND, Voltage_V=550V
J9: library part CMP-0087935-1, "Board-To-Board Connector, SSW Series, 32 Contacts, Receptacle, 2.54 mm, Through Hole, 3 Rows", Current_A=4.7A, Manufacturer=Samtec, Voltage_V=655V
J10: library part CMP-0079472-1, "DC POWER JACK, R/A, TH", Color=Black, Current_A=8A, Manufacturer="CUI Inc.", Supplier Part Number 1=CP-063AH-ND, Voltage_V=24V
J11: library part CMP-0055293-1, "Connector, Receptacle, Micro-USB Type B, R/A, Bottom Mount SMT", Manufacturer=Molex, Supplier Part Number 1=WM1399CT-ND
L1: library part CMP-0003352-2, "Ferrite Bead, 120 ohm @ 100 MHz, 3 A, 0603", Manufacturer=MuRata, Supplier Part Number 1=490-3996-1-ND, Value1="0.025 ohm", Value2=3A, ValueDisplayed="120 ohm"
L2: library part CMP-0003396-1, "Ferrite Bead, 800 ohm @ 100 MHz, 8 A, 2220", Manufacturer="Laird-Signal Integrity Products", Supplier Part Number 1=240-2433-1-ND, Value1="0.01 ohm", Value2=8A, ValueDisplayed="800 ohm"
L3: library part CMP-0013118-2, "Coupled inductor, 8 A, 0.006 ohm, SMD", Manufacturer=TDK, Supplier Part Number 1=445-2212-1-ND
L4: library part CMP-0090842-1, "Power Inductor, shielded, composite, 1uH 20% tol, DCR 7.2mOhms, SRF 65MHz, Isat 4.8A, Irms 13A, AEC-Q200", Manufacturer=Coilcraft, Operating Temperature Range="to +165°C", Self Resonant Frequency=65MHz, Test Frequency=1MHz, Tolerance_%=20%
L5 L6 L7 L16 L17 L23: library part CMP-0083745-1, "Inductor, Wirewound, Ferrite, 100 nH, 2.85 A, 0.024 ohm, AEC-Q200 Grade 1, SMD", Manufacturer=TDK, Value1="0.024 ohm", Value2=2.85A, ValueDisplayed=100nH
L8: library part CMP-0003428-2, "Ferrite Bead, 30 ohm @ 100 MHz, 6 A, 0805", Manufacturer=TDK, Supplier Part Number 1=445-1566-1-ND, Value1="0.01 ohm", Value2=6A, ValueDisplayed="30 ohm"
L10: library part CMP-0013193-2, "Coupled inductor, 100 uH,  A, 1.5 ohm, SMD", Manufacturer=TDK, Supplier Part Number 1=445-172386-1-ND, ValueDisplayed=100uH
L13 L14: library part CMP-0062430-2, "Inductor, Ferrite, 100 uH, 0.15 A, 2 ohm, SMD", Manufacturer=TDK, Supplier Part Number 1=445-3959-1-ND, Value1="2 ohm", Value2=0.15A, ValueDisplayed=100uH
L15: library part CMP-0061091-1, "Inductor, Shielded, Composite, 470 nH, 15.5 A, 0.0041 ohm, AEC-Q200 Grade 1, SMD", Manufacturer=Coilcraft, Value1="0.0041 ohm", Value2=15.5A, ValueDisplayed=470nH
L18 L19 L21 L22: library part CMP-0090526-1, "470nH Shielded Thin Film Inductor 4.9A 24mOhm Max 1008 (2520 Metric)", Digikey Part Number=445-181489-1-ND, Manufacturer=TDK, Mouser Part Number=810-TFM252012ALMAR47, Operating Temperature Range="-55°C to +150°C", Test Frequency=1MHz, Tolerance_%=20%
L20: library part CMP-0060997-1, "Inductor, Shielded, Composite, 560 nH, 13.9 A, 0.0083 ohm, AEC-Q200 Grade 1, SMD", Manufacturer=Coilcraft, Supplier Part Number 1=994-XAL5020-561MEB, Value1="0.0083 ohm", Value2=13.9A, ValueDisplayed=560nH
LBL1: library part CMP-0003625-1, "Thermal Transfer Printable Labels, 0.650\" W x 0.200\" H - 10,000 per roll", Manufacturer=Brady, Supplier Part Number 1=97C5133
Logo1: library part CMP-0074847-1, "FCC_disclaimer"
Logo2: library part CMP-0074838-1, "Texas Instrument Corporate Signature"
LOGO3: library part CMP-0074844-1
Logo4: library part CMP-0074769-1
MP1 MP2 MP3 MP4: library part CMP-0089174-1, Digikey Part Number=36-1902D-ND, Manufacturer="Keystone Electronics", Mouser Part Number=534-1902D, Operating Temperature Range=to
P1 P2: library part CMP-0075405-3, "Header, 100mil, 2x1, Gold, TH", Color=Black, Current_A=6.3A, Manufacturer=Samtec, Supplier Part Number 1=SAM1029-02-ND, Voltage_V=550V
R1 R2 R85 R86: library part CMP-0026699-1, "RES, 470, 1%, 0.1 W, AEC-Q200 Grade 0, 0402", Manufacturer=Panasonic, Power_W=100mW, Supplier Part Number 1=P470LCT-ND, TempCo="100 ppm/C", Tolerance_%=1%, Value2=0.1W, Value_Code=470R, ValueDisplayed=470
R3 R4 R5 R6 R7 R8 R9 R13 R14 R194: library part CMP-0026237-2, "RES, 2.49 k, 1%, 0.063 W, AEC-Q200 Grade 0, 0402", Manufacturer=Vishay-Dale, Power_W=63mW, Supplier Part Number 1=541-2.49KLCT-ND, TempCo="100 ppm/C", Tolerance_%=1%, Value2=0.063W, Value_Code=2k49, ValueDisplayed=2.49k
R10 R17 R24 R27 R30 R31 R35 R36 R53 R56 R58 R59 R62 R127 R128 R130 R136 R141 R144 R151 R152 R159 R160 R164 R165 R167 R170 R175 R176 R179 R180 R181 R185 R190 R202 R215 R224 R225: library part CMP-0025958-3, "RES, 10.0 k, 1%, 0.063 W, AEC-Q200 Grade 0, 0402", Manufacturer=Vishay-Dale, Power_W=63mW, Supplier Part Number 1=541-10.0KLCT-ND, TempCo="100 ppm/C", Tolerance_%=1%, Value2=0.063W, Value_Code=10k0, ValueDisplayed=10.0k
R11 R15: library part CMP-0026890-5, "RES, 2.2 k, 5%, 0.063 W, AEC-Q200 Grade 0, 0402", Manufacturer=Vishay-Dale, Power_W=63mW, Supplier Part Number 1=541-2.2KJCT-ND, TempCo="200 ppm/C", Tolerance_%=5%, Value2=0.063W, Value_Code=2k20, ValueDisplayed=2.2k
R12 R40 R41 R70 R83 R87 R88 R110 R113 R114 R115 R118 R120 R121 R125 R126 R129 R142 R143 R156 R158 R184 R193 R195 R199 R201 R203 R205 R206 R207 R208 R209 R210 R213 R216 R218 R219 R220 R221 R222 R223 R226 R227: library part CMP-0026822-3, "RES, 0, 5%, 0.063 W, AEC-Q200 Grade 0, 0402", Manufacturer=Vishay-Dale, Power_W=63mW, Supplier Part Number 1=541-0.0JCT-ND, TempCo="200 ppm/C", Tolerance_%=5%, Value2=0.063W, Value_Code=0000, ValueDisplayed=0
R16 R89 R90 R91 R92 R93 R94 R95 R97 R98 R99 R102 R104 R112 R132 R133 R134 R148 R149: library part CMP-0027275-3, "RES, 33.2, 1%, 0.05 W, 0201", Manufacturer=Vishay-Dale, Power_W=50mW, Supplier Part Number 1=541-33.2ABCT-ND, TempCo="200 ppm/C", Tolerance_%=1%, Value2=0.05W, Value_Code=33R2, ValueDisplayed=33.2
R18 R23 R33 R38: library part CMP-0026491-1, "RES, 61.9, 1%, 0.063 W, 0402", Manufacturer=Vishay-Dale, Power_W=63mW, Supplier Part Number 1=541-61.9LCT-ND, TempCo="100 ppm/C", Tolerance_%=1%, Value2=0.063W, Value_Code=61R9, ValueDisplayed=61.9
R19 R20 R21 R22 R46 R48 R49 R50 R146 R171 R172 R173 R174 R178 R186 R188 R189 R191 R192 R196 R197: library part CMP-0026825-4, "RES, 10 k, 5%, 0.063 W, 0402", Manufacturer=Vishay-Dale, Power_W=63mW, Supplier Part Number 1=541-10KJCT-ND, TempCo="200 ppm/C", Tolerance_%=5%, Value2=0.063W, Value_Code=10k0, ValueDisplayed=10k
R25 R29 R63 R204: library part CMP-0025950-3, "RES, 100 k, 1%, 0.063 W, AEC-Q200 Grade 0, 0402", Manufacturer=Vishay-Dale, Power_W=63mW, Supplier Part Number 1=541-100KLCT-ND, TempCo="100 ppm/C", Tolerance_%=1%, Value2=0.063W, Value_Code=100k
R26 R138: library part CMP-0026769-2, "RES, 10.0 k, 0.5%, 0.063 W, AEC-Q200 Grade 0, 0402", Manufacturer=Vishay-Dale, Power_W=63mW, Supplier Part Number 1=541-10KAVCT-ND, TempCo="50 ppm/C", Tolerance_%=0.5%, Value2=0.063W, Value_Code=10k0, ValueDisplayed=10.0k
R28 R137: library part CMP-0026162-2, "RES, 20.0 k, 1%, 0.063 W, AEC-Q200 Grade 0, 0402", Manufacturer=Vishay-Dale, Power_W=63mW, Supplier Part Number 1=541-20.0KLCT-ND, TempCo="100 ppm/C", Tolerance_%=1%, Value2=0.063W, Value_Code=20k0, ValueDisplayed=20.0k
R32 R47 R54 R105 R109 R161 R162 R168 R187: library part CMP-0027008-4, "RES, 0, 5%, 0.05 W, 0201", Manufacturer=Vishay-Dale, Power_W=50mW, Supplier Part Number 1=72M6743, TempCo=ppm/C, Tolerance_%=5%, Value2=0.05W, Value_Code=0000, ValueDisplayed=0
R34 R37 R73 R77 R78 R131 R139 R140 R145 R153 R154 R183: library part CMP-0026299-2, "RES, 33.2, 1%, 0.063 W, AEC-Q200 Grade 0, 0402", Manufacturer=Vishay-Dale, Power_W=63mW, Supplier Part Number 1=541-33.2LCT-ND, TempCo="100 ppm/C", Tolerance_%=1%, Value2=0.063W, Value_Code=33R2, ValueDisplayed=33.2
R39 R198 R200 R211: library part CMP-0026404-2, "RES, 49.9, 1%, 0.063 W, AEC-Q200 Grade 0, 0402", Manufacturer=Vishay-Dale, Power_W=63mW, Supplier Part Number 1=541-49.9LCT-ND, TempCo="100 ppm/C", Tolerance_%=1%, Value2=0.063W, Value_Code=49R9, ValueDisplayed=49.9
R42 R43 R76 R81 R155 R157: library part CMP-0026244-2, "RES, 2.94 k, 1%, 0.063 W, AEC-Q200 Grade 0, 0402", Manufacturer=Vishay-Dale, Power_W=63mW, Supplier Part Number 1=541-2.94KLCT-ND, TempCo="100 ppm/C", Tolerance_%=1%, Value2=0.063W, Value_Code=2k94, ValueDisplayed=2.94k
R44 R45 R229 R233: library part CMP-0025884-3, "RES, 0, 5%, 0.125 W, 0603", Manufacturer=Vishay/Beyschlag, Power_W=125mW, Supplier Part Number 1=MCT0603-0.0-ZZCT-ND, TempCo=ppm/C, Tolerance_%=5%, Value2=0.125W, Value_Code=0000, ValueDisplayed=0
R51: library part CMP-0026196-2, "RES, 24.9 k, 1%, 0.063 W, AEC-Q200 Grade 0, 0402", Manufacturer=Vishay-Dale, Power_W=63mW, Supplier Part Number 1=541-24.9KLCT-ND, TempCo="100 ppm/C", Tolerance_%=1%, Value2=0.063W, Value_Code=24k9, ValueDisplayed=24.9k
R52: library part CMP-0026658-1, "RES, 10.0 k, 1%, 0.1 W, 0402", Manufacturer=Panasonic, Power_W=100mW, Supplier Part Number 1=P10.0KLCT-ND, TempCo="100 ppm/C", Tolerance_%=1%, Value2=0.1W, Value_Code=10k0, ValueDisplayed=10.0k
R55: library part CMP-0022680-4, "RES, 1.00 k, 1%, 0.1 W, 0603", Manufacturer=Panasonic, PartNumber=ERJ-3EKF1001V, Power_W=100mW, Supplier Part Number 1=P1.00KHCT-ND, TempCo="100 ppm/C", Tolerance_%=1%, Value2=0.1W, Value_Code=1k00, ValueDisplayed=1.00k
R57: library part CMP-0026486-2, "RES, 60.4 k, 1%, 0.063 W, AEC-Q200 Grade 0, 0402", Manufacturer=Vishay-Dale, Power_W=63mW, Supplier Part Number 1=541-60.4KLCT-ND, TempCo="100 ppm/C", Tolerance_%=1%, Value2=0.063W, Value_Code=60k4, ValueDisplayed=60.4k
R60 R61: library part CMP-0026129-2, "RES, 1.00, 1%, 0.063 W, AEC-Q200 Grade 0, 0402", Manufacturer=Vishay-Dale, Power_W=63mW, Supplier Part Number 1=541-1.00LLCT-ND, TempCo="100 ppm/C", Tolerance_%=1%, Value2=0.063W, Value_Code=1R00, ValueDisplayed=1.00
R64 R75 R80 R82 R135 R228 R234 R235: library part CMP-0026992-3, "RES, 0, 5%, 0.1 W, AEC-Q200 Grade 0, 0402", Manufacturer=Panasonic, Power_W=100mW, Supplier Part Number 1=P0.0JCT-ND, TempCo="600 ppm/C", Tolerance_%=5%, Value2=0.1W, Value_Code=0000, ValueDisplayed=0
R65 R67 R69 R71 R79 R101 R107 R182 R241: library part CMP-0026071-3, "RES, 1.00 k, 1%, 0.063 W, AEC-Q200 Grade 0, 0402", Manufacturer=Vishay-Dale, Power_W=63mW, Supplier Part Number 1=541-1.00KLCT-ND, TempCo="100 ppm/C", Tolerance_%=1%, Value2=0.063W, Value_Code=1k00, ValueDisplayed=1.00k
R66: library part CMP-0026379-2, "RES, 43.2 k, 1%, 0.063 W, AEC-Q200 Grade 0, 0402", Manufacturer=Vishay-Dale, Power_W=63mW, Supplier Part Number 1=541-43.2KLCT-ND, TempCo="100 ppm/C", Tolerance_%=1%, Value2=0.063W, Value_Code=43k2, ValueDisplayed=43.2k
R68: library part CMP-0026414-2, "RES, 4.99 k, 1%, 0.063 W, AEC-Q200 Grade 0, 0402", Manufacturer=Vishay-Dale, Power_W=63mW, Supplier Part Number 1=541-4.99KLCT-ND, TempCo="100 ppm/C", Tolerance_%=1%, Value2=0.063W, Value_Code=4k99, ValueDisplayed=4.99k
R72: library part CMP-0026413-2, "RES, 4.87 k, 1%, 0.063 W, AEC-Q200 Grade 0, 0402", Manufacturer=Vishay-Dale, Power_W=63mW, Supplier Part Number 1=541-4.87KLCT-ND, TempCo="100 ppm/C", Tolerance_%=1%, Value2=0.063W, Value_Code=4k87, ValueDisplayed=4.87k
R74: library part CMP-0025958-3, "RES, 10.0 k, 1%, 0.063 W, AEC-Q200 Grade 0, 0402", Manufacturer=Vishay-Dale, PartNumber=CRCW040210K0FKED, Power_W=63mW, Supplier Part Number 1=541-10.0KLCT-ND, TempCo="100 ppm/C", Tolerance_%=1%, Value2=0.063W, Value_Code=10k0, ValueDisplayed=10.0k
R84: library part CMP-0026680-1, "RES, 220, 1%, 0.1 W, AEC-Q200 Grade 0, 0402", Manufacturer=Panasonic, Power_W=100mW, Supplier Part Number 1=P220LCT-ND, TempCo="100 ppm/C", Tolerance_%=1%, Value2=0.1W, Value_Code=220R, ValueDisplayed=220
R96: library part CMP-0020444-3, "RES, 100 k, 5%, 0.125 W, AEC-Q200 Grade 0, 0805", Manufacturer=Vishay-Dale, Power_W=125mW, Supplier Part Number 1=541-100KACT-ND, TempCo="200 ppm/C", Tolerance_%=5%, Value2=0.125W, Value_Code=100k
R100 R106: library part CMP-0026210-2, "RES, 26.7, 1%, 0.063 W, AEC-Q200 Grade 0, 0402", Manufacturer=Vishay-Dale, Power_W=63mW, Supplier Part Number 1=541-26.7LCT-ND, TempCo="100 ppm/C", Tolerance_%=1%, Value2=0.063W, Value_Code=26R7, ValueDisplayed=26.7
R103 R108 R236 R237: library part CMP-0023343-3, "RES, 0, 1%, 0.1 W, AEC-Q200 Grade 0, 0603", Manufacturer="Stackpole Electronics Inc", Power_W=100mW, Supplier Part Number 1=RMCF0603ZT0R00CT-ND, TempCo=ppm/C, Tolerance_%=1%, Value2=0.1W, Value_Code=0
R111 R123 R124: library part CMP-0026938-5, "RES, 4.7 k, 5%, 0.063 W, AEC-Q200 Grade 0, 0402", Manufacturer=Vishay-Dale, Power_W=63mW, Supplier Part Number 1=541-4.7KJCT-ND, TempCo="200 ppm/C", Tolerance_%=5%, Value2=0.063W, Value_Code=4k70, ValueDisplayed=4.7k
R116 R117: library part CMP-0026824-3, "RES, 100, 5%, 0.063 W, AEC-Q200 Grade 0, 0402", Manufacturer=Vishay-Dale, Power_W=63mW, Supplier Part Number 1=541-100JCT-ND, TempCo="200 ppm/C", Tolerance_%=5%, Value2=0.063W, Value_Code=100R, ValueDisplayed=100
R119: library part CMP-0022138-4, "RES, 1.00 M, 1%, 0.1 W, AEC-Q200 Grade 0, 0603", Manufacturer=Vishay-Dale, Power_W=100mW, Supplier Part Number 1=541-1.00MHCT-ND, TempCo="100 ppm/C", Tolerance_%=1%, Value2=0.1W, Value_Code=1M00, ValueDisplayed=1.00M
R122 R147: "RES, 10 k, 5%, 0.063 W, 0402", Manufacturer=Vishay-Dale, Power_W=0.063, Supplier Part Number 1=541-10KJCT-ND, TempCo="200 ppm/C", Tolerance_%=5, Value1=5%, Value2=0.063W, Value_Code=10k0, ValueDisplayed=10k
R150 R240: library part CMP-0026395-2, "RES, 47.5 k, 1%, 0.063 W, AEC-Q200 Grade 0, 0402", Manufacturer=Vishay-Dale, Power_W=63mW, Supplier Part Number 1=541-47.5KLCT-ND, TempCo="100 ppm/C", Tolerance_%=1%, Value2=0.063W, Value_Code=47k5, ValueDisplayed=47.5k
R163: library part CMP-0026907-3, "RES, 33 k, 5%, 0.063 W, AEC-Q200 Grade 0, 0402", Manufacturer=Vishay-Dale, Power_W=63mW, Supplier Part Number 1=541-33KJCT-ND, TempCo="200 ppm/C", Tolerance_%=5%, Value2=0.063W, Value_Code=33k0, ValueDisplayed=33k
R166: library part CMP-0026058-3, "RES, 18.0 k, 1%, 0.063 W, AEC-Q200 Grade 0, 0402", Manufacturer=Vishay-Dale, Power_W=63mW, Supplier Part Number 1=541-18.0KLCT-ND, TempCo="100 ppm/C", Tolerance_%=1%, Value2=0.063W, Value_Code=18k0, ValueDisplayed=18.0k
R169: library part CMP-0026918-5, "RES, 3.3 k, 5%, 0.063 W, AEC-Q200 Grade 0, 0402", Manufacturer=Vishay-Dale, Power_W=63mW, Supplier Part Number 1=541-3.3KJCT-ND, TempCo="200 ppm/C", Tolerance_%=5%, Value2=0.063W, Value_Code=3k30, ValueDisplayed=3.3k
R177: library part CMP-0026570-2, "RES, 80.6 k, 1%, 0.063 W, AEC-Q200 Grade 0, 0402", Manufacturer=Vishay-Dale, Power_W=63mW, Supplier Part Number 1=541-80.6KLCT-ND, TempCo="100 ppm/C", Tolerance_%=1%, Value2=0.063W, Value_Code=80k6, ValueDisplayed=80.6k
R212: library part CMP-0026993-2, "RES, 100, 5%, 0.1 W, AEC-Q200 Grade 0, 0402", Manufacturer=Panasonic, Power_W=100mW, Supplier Part Number 1=P100JCT-ND, TempCo="200 ppm/C", Tolerance_%=5%, Value2=0.1W, Value_Code=100R, ValueDisplayed=100
R214: library part CMP-0026219-2, "RES, 28.0 k, 1%, 0.063 W, AEC-Q200 Grade 0, 0402", Manufacturer=Vishay-Dale, Power_W=63mW, Supplier Part Number 1=541-28.0KLCT-ND, TempCo="100 ppm/C", Tolerance_%=1%, Value2=0.063W, Value_Code=28k0, ValueDisplayed=28.0k
R217: library part CMP-0026517-2, "RES, 6.81 k, 1%, 0.063 W, AEC-Q200 Grade 0, 0402", Manufacturer=Vishay-Dale, Power_W=63mW, Supplier Part Number 1=541-6.81KLCT-ND, TempCo="100 ppm/C", Tolerance_%=1%, Value2=0.063W, Value_Code=6k81, ValueDisplayed=6.81k
R230 R231: library part CMP-0078210-2, "RES, 330 k, 1%, 0.063 W, AEC-Q200 Grade 0, 0402", Manufacturer=Vishay-Dale, Power_W=63mW, Supplier Part Number 1=541-330KLCT-ND, TempCo="100 ppm/C", Tolerance_%=1%, Value2=0.063W, Value_Code=330k
R232: library part CMP-0078244-2, "RES, 30.0 k, 1%, 0.063 W, AEC-Q200 Grade 0, 0402", Manufacturer=Vishay-Dale, Power_W=63mW, Supplier Part Number 1=541-30.0KLCT-ND, TempCo="100 ppm/C", Tolerance_%=1%, Value2=0.063W, Value_Code=30k0, ValueDisplayed=30.0k
R238 R239: library part CMP-0086176-1, "RES, 0, 0.75 W, AEC-Q200 Grade 0, 1206", Manufacturer=Vishay-Dale, Power_W=750mW, Tolerance_%=0%, Value2=0.75W, Value_Code=0
S1 S2 S3: "Switch, Tactile, 12v, 50mA, Vertical, SMD", Alternate Manufacturer=Any, Alternate PartNumber=Equivalent, CurrentRating_mA=50, Manufacturer=Alps, Supplier Part Number 1=688-SKRKAE
TP1 TP28 TP41: "Test Point, Miniature, Black, TH", Manufacturer=Keystone, Supplier Part Number 1=5001K-ND
TP2 TP3 TP4 TP5 TP6 TP7 TP8 TP10 TP11 TP12 TP13 TP14 TP15 TP16 TP17 TP18 TP19 TP20 TP21 TP22 TP23 TP24 TP25 TP26 TP27 TP29 TP30 TP31 TP32 TP33 TP34 TP35 TP36 TP37 TP38 TP39 TP40 TP43: library part CMP-0003719-1, "Testpoint", Manufacturer="Texas Instruments"
TP9 TP42: "Test Point, Miniature, Red, TH", Manufacturer=Keystone, Supplier Part Number 1=5000K-ND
